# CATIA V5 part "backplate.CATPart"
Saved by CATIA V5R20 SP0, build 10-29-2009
Part number: backplate
Source: Unknown
Bounding box of the stored display mesh (mm): x -118.184 to 307.816, y 0 to 4, z 192.615 to 252.615
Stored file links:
  C:\Users\Ikarus\OneDrive - FH JOANNEUM\BAC - Arbeit 1\CAD Modell\CAD-Modell-Step files\Base\backplate.CATPart
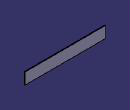
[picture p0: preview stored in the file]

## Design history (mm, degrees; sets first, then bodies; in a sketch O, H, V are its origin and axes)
Body1 (main body)
  Solid1 "Hauptkörper": solid without history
